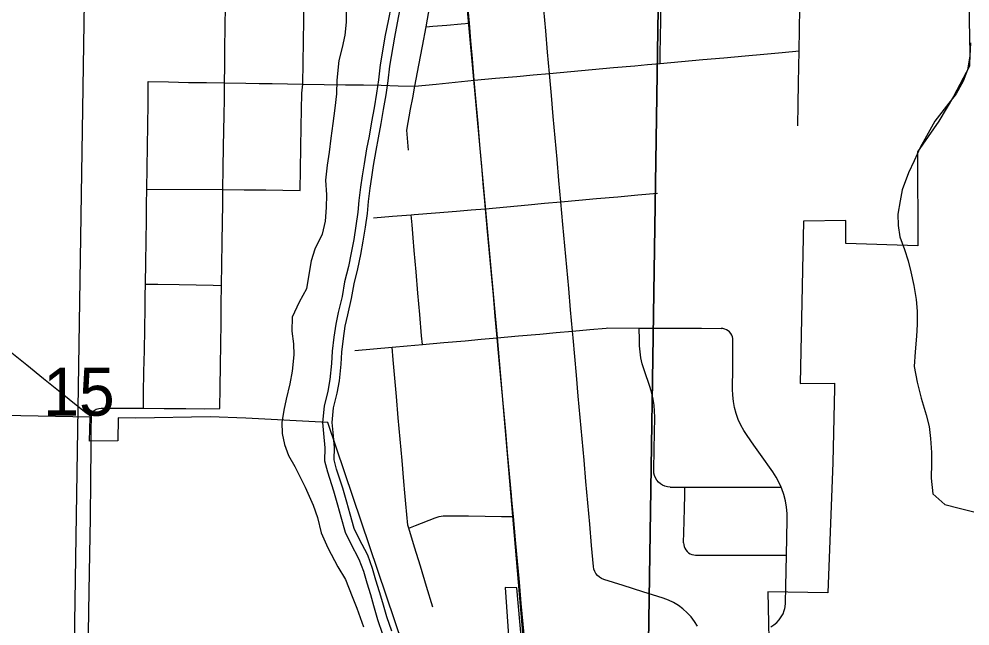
# Model space of a CAD drawing. Extents: x -11.1 to 34, y -3.9 to 22.
# Drawn here: x 4.812 to 5.641, y 15.573 to 16.102 of the extents above; entities that cross this region are included whole.
import ezdxf

# ---------------------------------------------------------------- set-up
doc = ezdxf.new("R2010")
doc.units = 0
for name, color, linetype in [('GM_X_City_Street', 7, 'Continuous'), ('GM_X_Corporation', 7, 'Continuous'), ('GM_X_County_Road', 7, 'Continuous'), ('GM_X_Minor_River', 7, 'Continuous'), ('GM_X_Rail_Line', 7, 'Continuous'), ('GM_X_Section_Text', 7, 'Continuous'), ('GM_X_State_Route', 7, 'Continuous')]:
    doc.layers.add(name, color=color, linetype=linetype)

msp = doc.modelspace()

# ---------------------------------------------------------------- linework, layer by layer
at = {"layer": 'GM_X_City_Street'}
for p, q in [((5.37945, 15.69395), (5.3924, 15.69394)), ((5.3924, 15.69394), (5.47621, 15.69385))]:
    msp.add_line(p, q, dxfattribs=at)
for points in [[(5.05932, 16.04538), (5.05962, 16.06402), (5.05991, 16.08266), (5.06021, 16.1013), (5.06051, 16.11994), (5.06067, 16.13014), (5.06084, 16.14034), (5.06098, 16.15615), (5.06115, 16.17479), (5.06132, 16.19343), (5.06148, 16.21207), (5.06165, 16.23071), (5.06175, 16.24245), (5.06185, 16.2542), (5.06192, 16.26175)], [(5.37074, 16.06341), (5.37094, 16.07382), (5.37113, 16.08423), (5.37148, 16.10287), (5.37183, 16.1215), (5.37218, 16.14014), (5.3725, 16.15723), (5.37282, 16.17433), (5.37318, 16.19296), (5.37343, 16.20637), (5.37368, 16.21978), (5.37399, 16.23637), (5.3743, 16.25297), (5.37445, 16.2607)], [(5.49079, 16.00909), (5.49113, 16.02773), (5.49146, 16.04637), (5.49172, 16.06033), (5.49197, 16.07429), (5.49231, 16.09293), (5.49265, 16.11157), (5.49297, 16.12934), (5.49329, 16.14712), (5.49381, 16.16085), (5.49433, 16.17458), (5.49439, 16.19322), (5.49446, 16.21186), (5.49463, 16.26186)], [(5.15139, 15.98784), (5.14988, 16.00512), (5.15332, 16.02344), (5.15519, 16.03348), (5.15708, 16.04351), (5.16049, 16.06184), (5.16362, 16.0786), (5.16675, 16.09536), (5.17019, 16.11367), (5.17364, 16.13199), (5.17617, 16.14548), (5.17871, 16.15898)], [(5.40328, 15.57255), (5.4007, 15.57677), (5.39772, 15.58072), (5.39438, 15.58437), (5.39071, 15.58767), (5.38673, 15.5906), (5.38249, 15.59315), (5.37802, 15.59527), (5.37338, 15.59695), (5.35561, 15.6026), (5.33864, 15.60801), (5.32166, 15.61341), (5.31966, 15.61423), (5.31784, 15.61538), (5.31623, 15.61681), (5.31487, 15.6185), (5.31383, 15.62039), (5.31311, 15.62242), (5.31274, 15.62454), (5.31108, 15.64311), (5.30942, 15.66168), (5.30776, 15.68024), (5.30611, 15.69881), (5.30445, 15.71738), (5.30279, 15.73594), (5.30114, 15.75451), (5.29948, 15.77308), (5.29782, 15.79164), (5.29638, 15.80792), (5.29492, 15.8242), (5.29441, 15.82999), (5.29274, 15.84856), (5.29108, 15.86713), (5.2894, 15.88569), (5.28774, 15.90426), (5.28607, 15.92283), (5.28517, 15.93279), (5.28428, 15.94274), (5.28263, 15.96131), (5.28098, 15.97987), (5.27934, 15.99844), (5.27769, 16.01701), (5.27604, 16.03557), (5.2752, 16.04515), (5.27435, 16.05474), (5.2727, 16.07331), (5.27106, 16.09188), (5.26941, 16.11044)], [(5.16675, 16.09536), (5.1727, 16.09587), (5.18501, 16.09694), (5.19732, 16.09801), (5.20449, 16.09863)], [(5.20882, 16.0488), (5.22739, 16.05049), (5.24595, 16.05217), (5.26015, 16.05346), (5.27435, 16.05474), (5.29291, 16.05641), (5.31148, 16.05809), (5.33005, 16.05975), (5.34861, 16.06142), (5.35968, 16.06242), (5.37074, 16.06341), (5.38931, 16.06508), (5.40787, 16.06674), (5.42644, 16.06841), (5.44501, 16.07007), (5.46105, 16.07151), (5.47708, 16.07295), (5.49197, 16.07429)], [(5.15708, 16.04351), (5.17562, 16.04541), (5.19222, 16.04711), (5.20882, 16.0488)], [(4.9204, 15.7627), (4.92057, 15.77579), (4.92089, 15.79443), (4.92121, 15.81307), (4.92152, 15.83171), (4.92183, 15.85036), (4.92201, 15.86069), (4.92218, 15.87103), (4.92245, 15.88968), (4.92272, 15.90832), (4.92298, 15.92696), (4.92317, 15.94033), (4.92337, 15.9537), (4.92363, 15.97234), (4.92388, 15.99098), (4.92414, 16.00962), (4.9244, 16.02826), (4.92453, 16.0379), (4.92467, 16.04753)], [(4.92467, 16.04753), (4.94218, 16.04724), (4.95969, 16.04694), (4.97543, 16.04668), (4.99117, 16.04642), (5.00981, 16.04614), (5.02124, 16.04596), (5.03267, 16.04579), (5.04599, 16.04558), (5.05932, 16.04538), (5.07796, 16.04512), (5.0966, 16.04488), (5.11218, 16.04466), (5.12777, 16.04445)], [(5.05702, 15.9526), (5.05733, 15.97124), (5.05765, 15.98988), (5.05796, 16.00853), (5.0582, 16.023), (5.05844, 16.03747), (5.05932, 16.04538)], [(5.12777, 16.04445), (5.14243, 16.04399), (5.15708, 16.04351)], [(4.92337, 15.9537), (4.98971, 15.95357), (5.00835, 15.9533), (5.02699, 15.95304), (5.04201, 15.95282), (5.05702, 15.9526)], [(5.21857, 15.93672), (5.23713, 15.93842), (5.25569, 15.94012), (5.26999, 15.94144), (5.28428, 15.94274), (5.29983, 15.94412), (5.31538, 15.9455), (5.33395, 15.94715), (5.35129, 15.94868), (5.36862, 15.95022)], [(5.12106, 15.92879), (5.13744, 15.93012), (5.15382, 15.93145), (5.15627, 15.93165), (5.17485, 15.93316), (5.19343, 15.93467), (5.206, 15.93569), (5.21857, 15.93672)], [(5.16359, 15.81832), (5.16293, 15.82594), (5.16133, 15.84451), (5.15972, 15.86308), (5.15812, 15.88165), (5.15651, 15.90023), (5.15554, 15.91144), (5.15457, 15.92266), (5.15382, 15.93145)], [(4.92218, 15.87103), (4.93288, 15.87084), (4.95152, 15.87049), (4.96637, 15.87021), (4.98122, 15.86993), (4.98849, 15.8698)], [(5.22879, 15.82405), (5.24736, 15.82573), (5.26592, 15.82741), (5.28016, 15.82871), (5.29441, 15.82999), (5.3096, 15.83137), (5.32378, 15.83265)], [(5.32378, 15.83265), (5.32479, 15.83275), (5.35253, 15.83263), (5.37117, 15.83255), (5.38981, 15.83247), (5.40684, 15.83239), (5.42387, 15.83232)], [(5.37945, 15.69395), (5.37721, 15.69413), (5.37502, 15.69466), (5.37295, 15.69553), (5.37103, 15.69672), (5.36933, 15.6982), (5.36789, 15.69992), (5.36673, 15.70185), (5.36589, 15.70395), (5.3654, 15.70614), (5.36526, 15.70839), (5.36557, 15.72703), (5.3658, 15.74098), (5.36603, 15.75493), (5.36594, 15.76021), (5.36548, 15.76548), (5.36467, 15.7707), (5.3635, 15.77586), (5.36197, 15.78092), (5.35677, 15.79631), (5.35524, 15.80137), (5.35408, 15.80652), (5.35326, 15.81175), (5.3528, 15.81701), (5.35271, 15.8223), (5.35253, 15.83263)], [(5.46722, 15.57217), (5.46992, 15.57381), (5.47239, 15.5758), (5.47455, 15.5781), (5.47641, 15.58066), (5.4779, 15.58345), (5.479, 15.58642), (5.47938, 15.58809), (5.4797, 15.5895), (5.47998, 15.59265), (5.48031, 15.60723), (5.48062, 15.62087), (5.48092, 15.63451), (5.48127, 15.64999), (5.48162, 15.66546), (5.48153, 15.671), (5.48099, 15.67651), (5.48002, 15.68196), (5.47862, 15.68731), (5.47679, 15.69254), (5.47621, 15.69385), (5.47456, 15.69761), (5.47193, 15.70248), (5.46892, 15.70713), (5.45818, 15.72237), (5.4524, 15.73057), (5.44662, 15.73877), (5.44367, 15.74331), (5.44109, 15.74807), (5.43889, 15.75301), (5.43707, 15.75811), (5.43566, 15.76333), (5.43466, 15.76865), (5.43407, 15.77403), (5.4339, 15.77944), (5.43405, 15.79809), (5.43415, 15.80995), (5.43425, 15.82182), (5.43413, 15.82345), (5.43376, 15.82505), (5.43315, 15.82656), (5.43229, 15.82797), (5.43124, 15.82922), (5.43, 15.83029), (5.42861, 15.83116), (5.4271, 15.83179), (5.42551, 15.83218), (5.42387, 15.83232)], [(5.10481, 15.81317), (5.12099, 15.81459), (5.13717, 15.81601), (5.15039, 15.81716), (5.16359, 15.81832), (5.18216, 15.81996), (5.20073, 15.82159), (5.21476, 15.82282), (5.22879, 15.82405)], [(5.17262, 15.58924), (5.16721, 15.60708), (5.16179, 15.62492), (5.15675, 15.64154), (5.15171, 15.65817), (5.15093, 15.66076), (5.14924, 15.67933), (5.14836, 15.689), (5.14748, 15.69866), (5.14585, 15.71723), (5.14422, 15.73579), (5.14259, 15.75436), (5.14096, 15.77293), (5.13956, 15.78888), (5.13816, 15.80482), (5.13717, 15.81601)], [(4.80436, 15.81213), (4.81886, 15.80042), (4.83336, 15.7887), (4.84786, 15.77699), (4.859, 15.768), (4.87013, 15.759), (4.87502, 15.75539)], [(5.39128, 15.64532), (5.39171, 15.66396), (5.39198, 15.67543), (5.39224, 15.68691), (5.3924, 15.69394)], [(5.15171, 15.65817), (5.15755, 15.66044), (5.17459, 15.66706), (5.17805, 15.66816), (5.18162, 15.6688), (5.18524, 15.66899), (5.20389, 15.66875), (5.21819, 15.66857), (5.2325, 15.66839), (5.24291, 15.66826)], [(5.39128, 15.64532), (5.39138, 15.64367), (5.39173, 15.64205), (5.39234, 15.64051), (5.39319, 15.63908), (5.39424, 15.63781), (5.39549, 15.63672), (5.39689, 15.63584), (5.39842, 15.63519), (5.40003, 15.6348), (5.40168, 15.63467), (5.48092, 15.63451)]]:
    msp.add_lwpolyline(points, dxfattribs=at)
at = {"layer": 'GM_X_Corporation'}
for points in [[(4.37464, 16.27278), (5.37154, 16.26384), (5.35589, 15.25381), (4.35794, 15.26693)], [(5.37154, 16.26384), (6.37749, 16.26912), (6.35776, 15.24973), (5.35589, 15.25381)]]:
    msp.add_lwpolyline(points, close=True, dxfattribs=at)
for points in [[(5.75053, 16.13569), (5.62364, 16.13692), (5.63978, 16.11542), (5.64074, 16.07199), (5.64059, 16.06095), (5.62652, 16.03449), (5.61366, 16.01296), (5.59502, 15.98619), (5.59549, 15.90423), (5.53265, 15.90643), (5.53265, 15.92651), (5.49583, 15.92586), (5.4928, 15.78435), (5.5229, 15.78442), (5.52277, 15.78008), (5.52138, 15.71525), (5.51698, 15.60181), (5.46481, 15.6027), (5.46608, 15.53397)], [(5.14671, 15.5557), (5.08126, 15.75038), (5.00955, 15.75416), (4.97854, 15.75517), (4.91389, 15.754), (4.89849, 15.75433), (4.89815, 15.7344), (4.87353, 15.73397), (4.87408, 15.75484), (4.73794, 15.75753)], [(5.26458, 15.39769), (5.24579, 15.60617), (5.23562, 15.60621), (5.24103, 15.53059)]]:
    msp.add_lwpolyline(points, dxfattribs=at)
at = {"layer": 'GM_X_County_Road'}
for points in [[(4.987, 15.76254), (4.98726, 15.78118), (4.98752, 15.79983), (4.98778, 15.81847), (4.98804, 15.83711), (4.98826, 15.85346), (4.98849, 15.8698), (4.98876, 15.88844), (4.98903, 15.90708), (4.9893, 15.92572), (4.98951, 15.93965), (4.98971, 15.95357), (4.99, 15.97221), (4.99029, 15.99085), (4.99051, 16.00454), (4.99072, 16.01823), (4.99094, 16.03233), (4.99117, 16.04642), (4.99131, 16.06143), (4.99146, 16.07643), (4.99165, 16.09507), (4.99184, 16.11371)], [(4.87494, 15.74318), (4.87502, 15.75539), (4.87562, 15.75818), (4.8763, 15.75969), (4.87755, 15.76076), (4.87916, 15.76195)], [(4.87916, 15.76195), (4.88143, 15.76248), (4.88369, 15.7627), (4.88753, 15.76278), (4.9057, 15.76274), (4.9204, 15.7627), (4.93835, 15.76255), (4.95742, 15.76233), (4.97356, 15.76225), (4.987, 15.76254)], [(4.86843, 15.25921), (4.86862, 15.27158), (4.8689, 15.29022), (4.86919, 15.30886), (4.86948, 15.3275), (4.86976, 15.34614), (4.87005, 15.36479), (4.87033, 15.38343), (4.87038, 15.40344), (4.87092, 15.43507), (4.87132, 15.47072), (4.87175, 15.51227), (4.87199, 15.53519), (4.87266, 15.56695), (4.87306, 15.60288), (4.87361, 15.63559), (4.87414, 15.66667), (4.87454, 15.70005), (4.87481, 15.72862), (4.87494, 15.74318)]]:
    msp.add_lwpolyline(points, dxfattribs=at)
at = {"layer": 'GM_X_Minor_River'}
for points in [[(5.13627, 16.11408), (5.1337, 16.10044), (5.13115, 16.08794), (5.1268, 16.06217), (5.12538, 16.04926), (5.12361, 16.03751), (5.12143, 16.02462), (5.11927, 16.01249), (5.1171, 15.99998), (5.11496, 15.989), (5.11278, 15.97573), (5.11104, 15.9655), (5.10968, 15.95564), (5.10829, 15.94387), (5.10731, 15.93362), (5.10553, 15.92187), (5.10375, 15.90974), (5.10161, 15.89837), (5.09906, 15.88626), (5.09574, 15.87302), (5.09356, 15.86013), (5.09022, 15.84614), (5.0881, 15.83591), (5.08633, 15.82454), (5.08493, 15.8124), (5.08432, 15.80176), (5.08287, 15.78772), (5.08113, 15.77749), (5.07781, 15.76464), (5.07636, 15.75022), (5.07728, 15.74069), (5.07853, 15.7281), (5.07828, 15.7167), (5.08072, 15.70713), (5.08605, 15.69065), (5.08957, 15.6784), (5.09238, 15.66807), (5.09626, 15.65467), (5.10098, 15.64505), (5.10826, 15.63119), (5.11219, 15.62045), (5.11501, 15.6105), (5.11819, 15.60015), (5.12102, 15.59058), (5.12454, 15.57833), (5.12881, 15.56569)], [(5.09713, 16.11081), (5.09726, 16.09938), (5.09588, 16.088), (5.09375, 16.07739), (5.09085, 16.06604), (5.08896, 16.04897), (5.08869, 16.03679), (5.08728, 16.02427), (5.08548, 16.01099), (5.08368, 15.9981), (5.08227, 15.98595), (5.08051, 15.97458), (5.07909, 15.96168), (5.07995, 15.94872), (5.0797, 15.93769), (5.07869, 15.92592), (5.07616, 15.91456), (5.06981, 15.9014), (5.06655, 15.8912), (5.06481, 15.88097), (5.0626, 15.86694), (5.05628, 15.85529), (5.04992, 15.84213), (5.04966, 15.82996), (5.05131, 15.81889), (5.05148, 15.80937), (5.05003, 15.79495), (5.04789, 15.78397), (5.04494, 15.77072), (5.04283, 15.76088), (5.04108, 15.75027), (5.04125, 15.74076), (5.04332, 15.7312), (5.0469, 15.72161), (5.05238, 15.71197), (5.06146, 15.69389), (5.06832, 15.67814), (5.07226, 15.6674), (5.07538, 15.65401), (5.08116, 15.64095), (5.0899, 15.62439), (5.09648, 15.61321), (5.10223, 15.59862), (5.10655, 15.58826), (5.11226, 15.57215)], [(5.13681, 15.56827), (5.13257, 15.58084), (5.12909, 15.59293), (5.12625, 15.60258), (5.12307, 15.61288), (5.1202, 15.62305), (5.11596, 15.63461), (5.10847, 15.64886), (5.10413, 15.65771), (5.10048, 15.67034), (5.09767, 15.68067), (5.09409, 15.69311), (5.0888, 15.70947), (5.08671, 15.71766), (5.08695, 15.72842), (5.08566, 15.7415), (5.08481, 15.75019), (5.08612, 15.76314), (5.08936, 15.77572), (5.09121, 15.78658), (5.0927, 15.80108), (5.09331, 15.81167), (5.09467, 15.8234), (5.09638, 15.8344), (5.09843, 15.84429), (5.10181, 15.85844), (5.10398, 15.87128), (5.10726, 15.88436), (5.10985, 15.89672), (5.11205, 15.90833), (5.11385, 15.92062), (5.11566, 15.93258), (5.11665, 15.94297), (5.11803, 15.95456), (5.11935, 15.96421), (5.12107, 15.97433), (5.12324, 15.9875), (5.12537, 15.99845), (5.12755, 16.01103), (5.12972, 16.02317), (5.13191, 16.03617), (5.13372, 16.04816), (5.13513, 16.061), (5.13942, 16.08639), (5.14195, 16.09881), (5.14452, 16.11242)], [(5.64145, 16.08139), (5.64077, 16.06962), (5.63858, 16.05789), (5.63491, 16.0481), (5.62894, 16.03685), (5.62031, 16.02605), (5.61012, 16.01301), (5.60295, 15.99988), (5.59739, 15.99014), (5.59216, 15.97849), (5.58734, 15.96797), (5.58166, 15.95329), (5.57989, 15.94346), (5.57808, 15.9321), (5.5782, 15.92221), (5.57985, 15.91228), (5.58373, 15.90116), (5.58689, 15.89119), (5.58931, 15.88162), (5.59203, 15.86977), (5.594, 15.85755), (5.59487, 15.84726), (5.59496, 15.83586), (5.59432, 15.82561), (5.59321, 15.81196), (5.59212, 15.79906), (5.5948, 15.78531), (5.59824, 15.77153), (5.60279, 15.75697), (5.60518, 15.74665), (5.60644, 15.73635), (5.60726, 15.72417), (5.6074, 15.71467), (5.60706, 15.70175), (5.60861, 15.68803), (5.61899, 15.67864), (5.63143, 15.67565), (5.64424, 15.67228)]]:
    msp.add_lwpolyline(points, dxfattribs=at)
at = {"layer": 'GM_X_Rail_Line'}
for points in [[(4.83755, 14.09996), (4.84005, 14.24738), (4.85562, 15.25898), (4.87136, 16.26658), (4.87826, 16.70806), (4.89599, 17.85935), (4.89412, 17.93146), (4.88952, 17.98439), (4.8767, 18.04189), (4.68365, 18.67523), (4.66078, 18.75097), (4.64705, 18.79843), (4.63971, 18.85502), (4.64675, 19.28767), (4.67685, 20.63104), (4.68041, 20.82286), (4.68184, 20.89996)], [(4.87801, 16.70783), (4.92664, 16.63771), (4.92939, 16.61489), (5.06087, 16.61224), (5.05979, 16.4614), (5.05905, 16.26479), (5.18891, 16.25889), (5.22866, 15.82439), (5.27609, 15.27216), (5.27847, 15.2153), (5.26663, 14.92751), (5.27495, 14.79199), (5.30526, 14.66939), (5.32778, 14.63192)]]:
    msp.add_lwpolyline(points, dxfattribs=at)
at = {"layer": 'GM_X_State_Route'}
for points in [[(5.21772, 15.94649), (5.21696, 15.95529), (5.21534, 15.97387), (5.21373, 15.99244), (5.21211, 16.01101), (5.2105, 16.02958), (5.20966, 16.0392), (5.20882, 16.0488), (5.2072, 16.06738), (5.20585, 16.083), (5.20449, 16.09863), (5.20287, 16.1172), (5.20185, 16.12893)], [(5.24158, 15.68292), (5.24122, 15.68683), (5.23954, 15.7054), (5.23786, 15.72396), (5.23617, 15.74253), (5.23449, 15.7611), (5.23281, 15.77966), (5.23113, 15.79823), (5.22996, 15.81114), (5.22879, 15.82405), (5.22711, 15.84262), (5.22542, 15.86119), (5.22374, 15.87975), (5.22205, 15.89832), (5.22037, 15.91689), (5.21948, 15.9268), (5.21857, 15.93672), (5.21772, 15.94649)], [(5.24696, 15.62357), (5.24642, 15.62943), (5.24474, 15.648), (5.24382, 15.65813), (5.24291, 15.66826), (5.24158, 15.68292)], [(5.25301, 15.5562), (5.2514, 15.57425), (5.24979, 15.5923), (5.24811, 15.61087), (5.24696, 15.62357)]]:
    msp.add_lwpolyline(points, dxfattribs=at)

# ---------------------------------------------------------------- texts
at = {"layer": 'GM_X_Section_Text'}
msp.add_text('15', height=0.041856, rotation=0.00001, dxfattribs=at).set_placement((4.8331, 15.75618))

doc.saveas('drawing.dxf')
